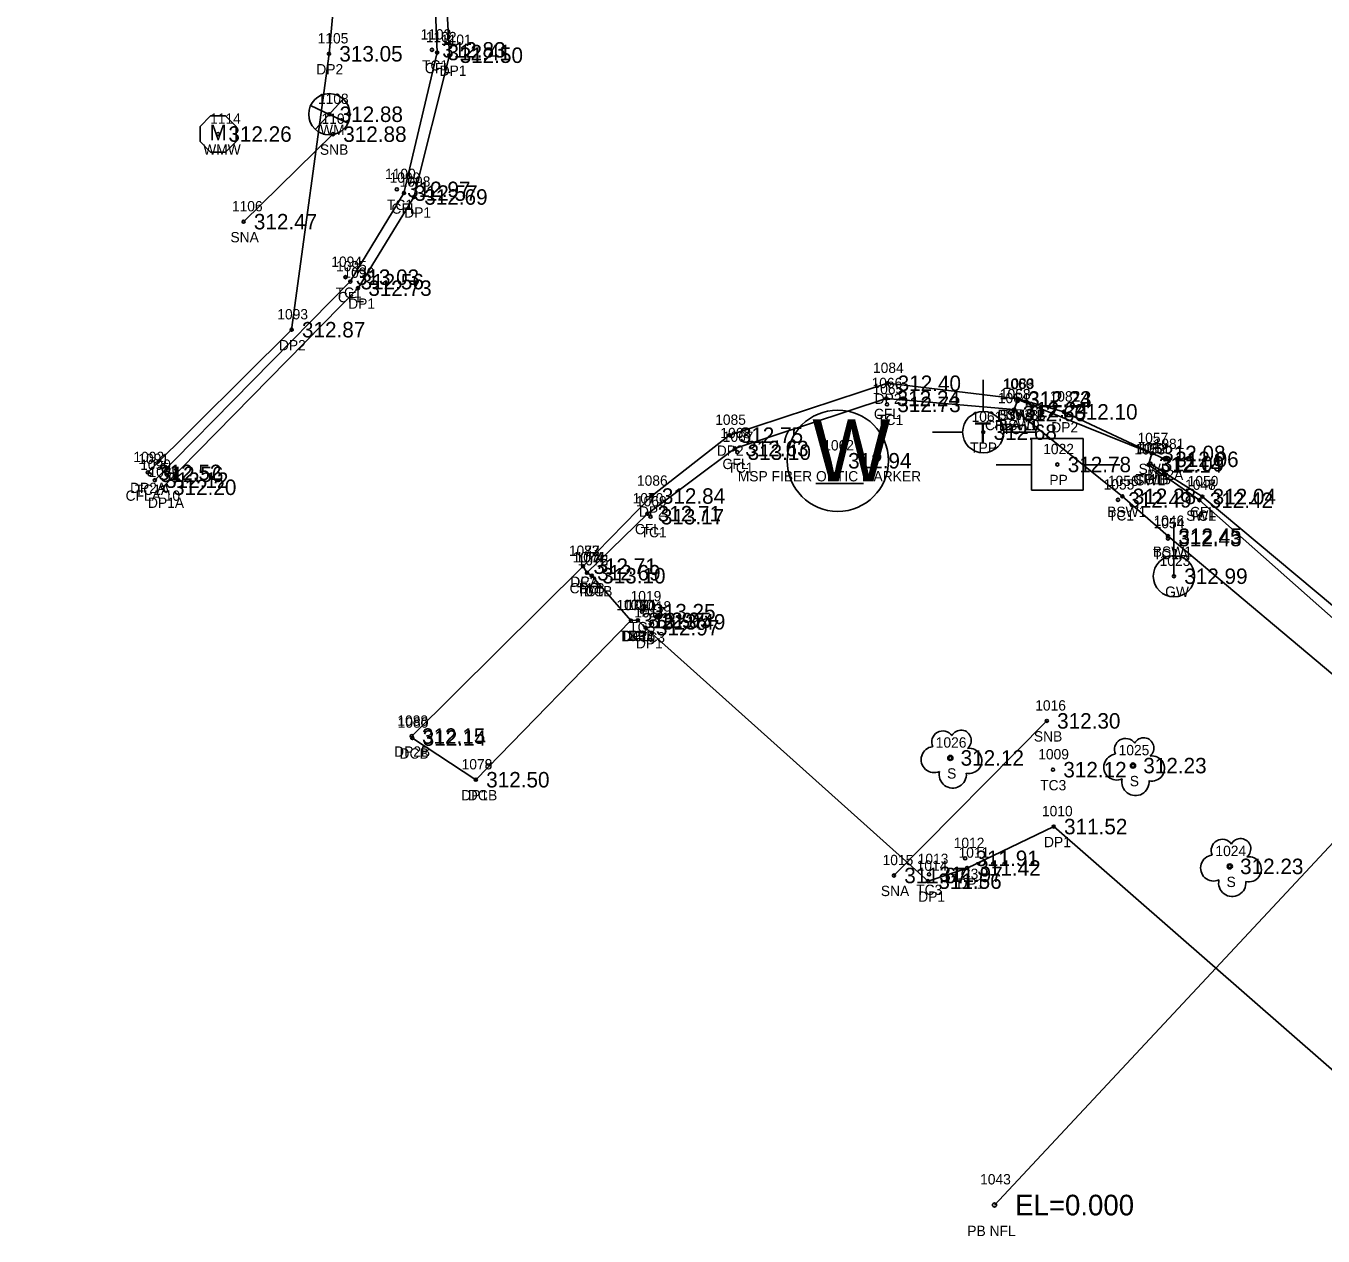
# Model space of a CAD drawing. Extents: x 1970076 to 1971136, y 803126 to 804215.
# Drawn here: x 1970842 to 1970967.7, y 803126.3 to 803243.6 of the extents above; entities that cross this region are included whole.
import ezdxf

# ---------------------------------------------------------------- set-up
doc = ezdxf.new("R2010")
doc.units = 0
for name, color, linetype in [('RD_EX_BldgApp', 7, 'Continuous'), ('RD_EX_BldgApp_txCode', 7, 'Continuous'), ('RD_EX_Conc', 7, 'Continuous'), ('RD_EX_Conc_txCode', 7, 'Continuous'), ('RD_EX_DR_Pipe', 7, 'Continuous'), ('RD_EX_DR_Pipe_txCode', 7, 'Continuous'), ('RD_EX_Driveway', 7, 'Continuous'), ('RD_EX_Driveway_txCode', 7, 'Continuous'), ('RD_EX_Misc_txCode', 7, 'Continuous'), ('RD_EX_SU_H2O', 7, 'Continuous'), ('RD_EX_TX_BldgApp_ELEV', 7, 'Continuous'), ('RD_EX_TX_Conc_ELEV', 7, 'Continuous'), ('RD_EX_TX_Driveway_ELEV', 7, 'Continuous'), ('RD_EX_TX_Misc_ELEV', 7, 'Continuous'), ('RD_EX_TX_UT_ELEV', 7, 'Continuous'), ('RD_EX_TX_VEG_ELEV', 7, 'Continuous'), ('RD_EX_UT', 7, 'Continuous'), ('RD_EX_UT_txCode', 7, 'Continuous'), ('RD_EX_VEG', 7, 'Continuous'), ('RD_EX_VEG_txCode', 7, 'Continuous'), ('RD_HC_Survey_ELEV', 7, 'Continuous'), ('RD_SMD_Locator', 7, 'Continuous'), ('RD_TX_Pipe_ElevEX', 7, 'Continuous')]:
    doc.layers.add(name, color=color, linetype=linetype)

msp = doc.modelspace()

# ---------------------------------------------------------------- linework, layer by layer
at = {"layer": 'RD_EX_BldgApp'}
for p, q in [((1970863.09, 803224.6), (1970871.75, 803233.08)), ((1970926.11, 803161.24), (1970940.92, 803176.22))]:
    msp.add_line(p, q, dxfattribs=at)
at = {"layer": 'RD_EX_Conc'}
for points in [[(1970854.49, 803199.55), (1970873.43, 803218.79), (1970878.63, 803227.37), (1970881.85, 803240.99), (1970881.47, 803250.65), (1970879.58, 803257.38)], [(1970937.76, 803206.39), (1970925.37, 803207.47), (1970910.7, 803202.62), (1970902.22, 803196.3), (1970896.36, 803190.58)], [(1970991.98, 803159.92), (1970984.78, 803166.48), (1970978.42, 803171.68), (1970975.48, 803174.25), (1970971.05, 803178.67), (1970952.67, 803194.12), (1970948.25, 803197.98), (1970937.76, 803206.39), (1970938.1, 803207.37)], [(1970994.79, 803163.51), (1970987.7, 803169.73), (1970983.17, 803172.25), (1970978.99, 803172.48), (1970976.18, 803174.83), (1970975.61, 803177.74), (1970973.48, 803181.89), (1970955.71, 803197.61), (1970950.79, 803201.04), (1970951.1, 803202.14), (1970938.1, 803207.37)], [(1970974.14, 803182.78), (1970955.99, 803197.96), (1970950.97, 803201.14)], [(1970895.99, 803191.21), (1970896.36, 803190.58), (1970896.84, 803190.29), (1970900.63, 803185.94), (1970885.6, 803170.52), (1970879.45, 803174.56)]]:
    msp.add_lwpolyline(points, dxfattribs=at)
at = {"layer": 'RD_EX_DR_Pipe'}
msp.add_line((1970977.83, 803174.26), (1970935.85, 803129.3), dxfattribs=at)
at = {"layer": 'RD_EX_Driveway'}
for points in [[(1970853.81, 803200.3), (1970867.75, 803214.13), (1970871.37, 803240.87), (1970873.32, 803262.28), (1970865.32, 803269.32), (1970865.67, 803269.64), (1970816.24, 803313.45)], [(1970855.26, 803198.86), (1970874.18, 803218.16), (1970879.6, 803226.99), (1970883.03, 803240.73), (1970882.49, 803250.86), (1970880.97, 803256.43), (1970880.48, 803257.86), (1970879.31, 803260.18), (1970873.44, 803270.12)], [(1970952.37, 803201.57), (1970942.58, 803206.17), (1970938.12, 803207.42), (1970925.47, 803208.94), (1970910.17, 803203.91), (1970902.62, 803198.01), (1970895.99, 803191.21), (1970879.38, 803174.75)], [(1970971.84, 803139.57), (1970941.59, 803165.98), (1970933.19, 803161.96), (1970929.41, 803160.69), (1970902.05, 803185.25), (1970901.29, 803185.97), (1970900.63, 803185.94), (1970885.6, 803170.52)]]:
    msp.add_lwpolyline(points, dxfattribs=at)
at = {"layer": 'RD_EX_SU_H2O'}
msp.add_lwpolyline([(1970862.38, 803232.37), (1970862.38, 803233.82), (1970861.35, 803234.85), (1970859.9, 803234.85), (1970858.87, 803233.82), (1970858.87, 803232.37), (1970859.9, 803231.34), (1970861.35, 803231.34)], close=True, dxfattribs=at)
at = {"layer": 'RD_EX_UT'}
for p, q in [((1970870.05, 803233.55), (1970872.72, 803236.45)), ((1970869.57, 803235.85), (1970873.2, 803234.14)), ((1970934.76, 803209.27), (1970934.76, 803206.2)), ((1970929.83, 803204.21), (1970932.76, 803204.21)), ((1970936.76, 803204.21), (1970939.83, 803204.21)), ((1970944.44, 803203.58), (1970939.44, 803203.58)), ((1970939.44, 803203.58), (1970939.44, 803198.58)), ((1970944.44, 803198.58), (1970944.44, 803203.58)), ((1970936.01, 803201.02), (1970939.48, 803201.02)), ((1970944.37, 803201.02), (1970948.01, 803201.02)), ((1970918.54, 803199.22), (1970923.17, 803199.22)), ((1970939.44, 803198.58), (1970944.44, 803198.58)), ((1970953.24, 803190.24), (1970953.24, 803195.24))]:
    msp.add_line(p, q, dxfattribs=at)
for centre, radius in [((1970871.4, 803235.01), 2), ((1970920.67, 803201.43), 4.91), ((1970934.76, 803204.2), 2), ((1970953.24, 803190.24), 2)]:
    msp.add_circle(centre, radius, dxfattribs=at)
at = {"layer": 'RD_EX_VEG'}
for centre in [(1970931.57, 803172.63), (1970949.27, 803171.89), (1970958.65, 803162.12)]:
    msp.add_circle(centre, 0.25, dxfattribs=at)
for centre, radius, start, end in [((1970930.85, 803174.17), 1.08, 34.9763, 204.756), ((1970932.61, 803174.33), 0.995, 308.7626, 152.0467), ((1970930, 803172.47), 1.26, 96.4518, 294.734), ((1970948.55, 803173.44), 1.08, 34.9763, 204.756), ((1970950.31, 803173.59), 0.995, 308.7626, 152.0467), ((1970933.41, 803172.35), 1.22, 256.5667, 98.1046), ((1970947.7, 803171.74), 1.26, 96.4518, 294.734), ((1970951.11, 803171.61), 1.22, 256.5667, 98.1046), ((1970931.81, 803171.03), 1.32, 166.8827, 5.7589), ((1970949.51, 803170.3), 1.32, 166.8827, 5.7589), ((1970959.69, 803163.82), 0.995, 308.7626, 152.0467), ((1970957.93, 803163.67), 1.08, 34.9763, 204.756), ((1970957.08, 803161.96), 1.26, 96.4518, 294.734), ((1970960.49, 803161.84), 1.22, 256.5667, 98.1046), ((1970958.89, 803160.52), 1.32, 166.8827, 5.7589)]:
    msp.add_arc(centre, radius, start, end, dxfattribs=at)
at = {"layer": 'RD_SMD_Locator'}
for centre, radius in [((1970871.37, 803240.87), 0.15), ((1970881.34, 803241.25), 0.15), ((1970881.85, 803240.99), 0.15), ((1970883.03, 803240.73), 0.15), ((1970871.4, 803235.01), 0.15), ((1970860.62, 803233.09), 0.15), ((1970871.75, 803233.08), 0.15), ((1970877.94, 803227.73), 0.15), ((1970878.63, 803227.37), 0.15), ((1970879.6, 803226.99), 0.15), ((1970863.09, 803224.6), 0.15), ((1970872.97, 803219.22), 0.15), ((1970873.43, 803218.79), 0.15), ((1970874.18, 803218.16), 0.15), ((1970867.75, 803214.13), 0.15), ((1970925.47, 803208.94), 0.15), ((1970925.37, 803207.47), 0.15), ((1970938.12, 803207.42), 0.15), ((1970925.44, 803206.89), 0.15), ((1970937.76, 803206.39), 0.15), ((1970937.76, 803206.39), 0.15), ((1970938.1, 803207.37), 0.15), ((1970938.1, 803207.37), 0.15), ((1970942.58, 803206.17), 0.15), ((1970937.59, 803206.01), 0.15), ((1970910.17, 803203.91), 0.15), ((1970934.76, 803204.2), 0.15), ((1970910.7, 803202.62), 0.15), ((1970910.93, 803202.26), 0.15), ((1970950.97, 803201.14), 0.15), ((1970950.97, 803201.14), 0.15), ((1970951.1, 803202.14), 0.15), ((1970952.37, 803201.57), 0.15), ((1970853.81, 803200.3), 0.15), ((1970854, 803200.12), 0.15), ((1970941.95, 803201.07), 0.15), ((1970950.79, 803201.04), 0.15), ((1970854.49, 803199.55), 0.15), ((1970855.26, 803198.86), 0.15), ((1970902.62, 803198.01), 0.15), ((1970947.82, 803197.64), 0.15), ((1970948.25, 803197.98), 0.15), ((1970955.71, 803197.61), 0.15), ((1970955.71, 803197.61), 0.15), ((1970955.99, 803197.96), 0.15), ((1970902.22, 803196.3), 0.15), ((1970902.52, 803196.01), 0.15), ((1970952.66, 803193.89), 0.15), ((1970952.67, 803194.12), 0.15), ((1970895.99, 803191.21), 0.15), ((1970895.99, 803191.21), 0.15), ((1970896.36, 803190.58), 0.15), ((1970896.36, 803190.58), 0.15), ((1970896.84, 803190.29), 0.15), ((1970896.84, 803190.29), 0.15), ((1970953.24, 803190.24), 0.15), ((1970901.69, 803186.81), 0.15), ((1970900.63, 803185.94), 0.15), ((1970900.63, 803185.94), 0.15), ((1970901.29, 803185.97), 0.15), ((1970901.29, 803185.97), 0.15), ((1970902.05, 803185.25), 0.15), ((1970902.64, 803185.82), 0.15), ((1970940.92, 803176.22), 0.15), ((1970879.38, 803174.75), 0.15), ((1970879.45, 803174.56), 0.15), ((1970931.57, 803172.63), 0.15), ((1970941.52, 803171.49), 0.15), ((1970949.27, 803171.89), 0.15), ((1970885.6, 803170.52), 0.15), ((1970885.6, 803170.52), 0.15), ((1970941.59, 803165.98), 0.15), ((1970933.01, 803162.9), 0.15), ((1970926.11, 803161.24), 0.15), ((1970929.51, 803161.35), 0.15), ((1970933.19, 803161.96), 0.15), ((1970958.65, 803162.12), 0.15), ((1970929.41, 803160.69), 0.15), ((1970935.85, 803129.3), 0.2)]:
    msp.add_circle(centre, radius, dxfattribs=at)

# ---------------------------------------------------------------- texts
at = {"layer": 'RD_EX_BldgApp_txCode'}
for s, p in [('1107', (1970870.64, 803234.08)), ('SNB', (1970870.49, 803231.08)), ('1106', (1970861.96, 803225.6)), ('SNA', (1970861.82, 803222.6)), ('1016', (1970939.8, 803177.22)), ('SNB', (1970939.67, 803174.22)), ('1015', (1970925.01, 803162.24)), ('SNA', (1970924.84, 803159.24))]:
    msp.add_text(s, height=1, dxfattribs=at).set_placement(p)
at = {"layer": 'RD_EX_Conc_txCode'}
for s, p in [('1103', (1970880.24, 803242.25)), ('1102', (1970880.75, 803241.99)), ('TC1', (1970880.38, 803239.25)), ('CFL', (1970880.65, 803238.99)), ('1100', (1970876.8, 803228.73)), ('1099', (1970877.24, 803228.37)), ('TC1', (1970876.98, 803225.73)), ('CFL', (1970877.42, 803225.37)), ('1094', (1970871.59, 803220.22)), ('1095', (1970872.05, 803219.79)), ('TC1', (1970872.01, 803217.22)), ('CFL', (1970872.23, 803216.79)), ('1066', (1970923.94, 803208.47)), ('1065', (1970924.03, 803207.89)), ('1060', (1970936.65, 803208.37)), ('1059', (1970936.71, 803208.37)), ('1064', (1970936.18, 803207.01)), ('1063', (1970936.36, 803207.39)), ('1058', (1970936.38, 803207.39)), ('CFL', (1970924.17, 803205.47)), ('BSW1B', (1970936.14, 803205.37)), ('SWLB', (1970936.33, 803205.37)), ('TC1', (1970924.48, 803204.89)), ('CFLA 10', (1970934.93, 803204.39)), ('BSW1', (1970936.28, 803204.39)), ('TC1', (1970936.62, 803204.01)), ('1068', (1970909.29, 803203.62)), ('1067', (1970909.52, 803203.26)), ('1057', (1970949.71, 803203.14)), ('1053', (1970949.4, 803202.04)), ('1052', (1970949.59, 803202.14)), ('1051', (1970949.87, 803202.14)), ('1091', (1970852.89, 803201.12)), ('1090', (1970853.07, 803200.55)), ('CFL', (1970909.49, 803200.62)), ('TC1', (1970909.97, 803200.26)), ('1056', (1970946.84, 803198.98)), ('CFLB', (1970949.29, 803199.14)), ('SWL', (1970949.5, 803199.04)), ('TC1B', (1970949.54, 803199.14)), ('SWL', (1970949.81, 803200.14)), ('TC1A', (1970852.55, 803198.12)), ('1055', (1970946.43, 803198.64)), ('1047', (1970954.32, 803198.61)), ('1048', (1970954.32, 803198.61)), ('1050', (1970954.57, 803198.96)), ('CFLA 10', (1970851.66, 803197.55)), ('1070', (1970900.79, 803197.3)), ('1069', (1970901.11, 803197.01)), ('BSW1', (1970946.77, 803195.98)), ('TC1', (1970946.85, 803195.64)), ('SWL', (1970954.42, 803195.61)), ('TC1', (1970954.75, 803195.61)), ('CFL', (1970954.79, 803195.96)), ('CFL', (1970901.01, 803194.3)), ('TC1', (1970901.56, 803194.01)), ('1046', (1970951.26, 803195.12)), ('1054', (1970951.27, 803194.89)), ('1073', (1970894.61, 803192.21)), ('1074', (1970894.97, 803191.58)), ('1071', (1970895.26, 803191.58)), ('TC1A', (1970951.21, 803191.89)), ('BSW1', (1970951.19, 803192.12)), ('1072', (1970895.46, 803191.29)), ('1075', (1970895.46, 803191.29)), ('DCA', (1970894.73, 803189.21)), ('CFLB', (1970894.68, 803188.58)), ('TC1B', (1970895.41, 803188.29)), ('DC', (1970895.58, 803188.58)), ('DC', (1970896.06, 803188.29)), ('1019', (1970900.59, 803187.81)), ('1076', (1970899.22, 803186.94)), ('1020', (1970899.86, 803186.97)), ('1018', (1970901.54, 803186.82)), ('TC3B', (1970899.57, 803183.97)), ('DC', (1970899.85, 803183.94)), ('TC3', (1970900.45, 803184.81)), ('TC3', (1970901.4, 803183.82)), ('1080', (1970878.03, 803175.56)), ('DCB', (1970878.2, 803172.56)), ('1079', (1970884.22, 803171.52)), ('1009', (1970940.09, 803172.49)), ('TC3', (1970940.28, 803169.49)), ('DC', (1970884.82, 803168.52)), ('1012', (1970931.9, 803163.9)), ('1013', (1970928.41, 803162.35)), ('TC3', (1970931.76, 803160.9)), ('TC3', (1970928.27, 803159.35))]:
    msp.add_text(s, height=1, dxfattribs=at).set_placement(p)
at = {"layer": 'RD_EX_DR_Pipe_txCode'}
for s, p in [('1043', (1970934.46, 803131.3)), ('PB NFL', (1970933.22, 803126.3))]:
    msp.add_text(s, height=1, dxfattribs=at).set_placement(p)
at = {"layer": 'RD_EX_Driveway_txCode'}
for s, p in [('1105', (1970870.27, 803241.87)), ('1101', (1970882.22, 803241.73)), ('DP2', (1970870.14, 803238.87)), ('DP1', (1970882.09, 803238.73)), ('1098', (1970878.22, 803227.99)), ('DP1', (1970878.66, 803224.99)), ('1096', (1970872.77, 803219.16)), ('DP1', (1970873.23, 803216.16)), ('1093', (1970866.36, 803215.13)), ('DP2', (1970866.52, 803212.13)), ('1084', (1970924.08, 803209.94)), ('1083', (1970936.73, 803208.42)), ('DP2', (1970924.24, 803206.94)), ('1082', (1970941.19, 803207.17)), ('DP2', (1970936.89, 803205.42)), ('1085', (1970908.79, 803204.91)), ('DP2', (1970941.35, 803204.17)), ('DP2', (1970908.94, 803201.91)), ('1081', (1970951.27, 803202.57)), ('1092', (1970852.42, 803201.3)), ('1089', (1970853.88, 803199.86)), ('1086', (1970901.21, 803199.01)), ('DP2A', (1970950.65, 803199.57)), ('DP2A', (1970852.09, 803198.3)), ('DP1A', (1970853.83, 803196.86)), ('DP2', (1970901.4, 803196.01)), ('1087', (1970894.61, 803192.21)), ('DP2', (1970894.76, 803189.21)), ('1077', (1970899.24, 803186.94)), ('1021', (1970900.18, 803186.97)), ('1017', (1970900.95, 803186.25)), ('DP1', (1970899.68, 803183.94)), ('DP1', (1970900.34, 803183.97)), ('DP1', (1970901.11, 803183.25)), ('1088', (1970877.99, 803175.75)), ('DP2B', (1970877.68, 803172.75)), ('1078', (1970884.22, 803171.52)), ('DP1B', (1970884.18, 803168.52)), ('1010', (1970940.45, 803166.98)), ('DP1', (1970940.65, 803163.98)), ('1011', (1970932.37, 803162.96)), ('1014', (1970928.31, 803161.69)), ('DP1', (1970932.25, 803159.96)), ('DP1', (1970928.46, 803158.69))]:
    msp.add_text(s, height=1, dxfattribs=at).set_placement(p)
at = {"layer": 'RD_EX_Misc_txCode'}
for s, p in [('1114', (1970859.85, 803234.09)), ('WMW', (1970859.18, 803231.09)), ('1062', (1970919.26, 803202.43)), ('MSP FIBER OPTIC MARKER', (1970910.98, 803199.43))]:
    msp.add_text(s, height=1, dxfattribs=at).set_placement(p)
at = {"layer": 'RD_EX_SU_H2O'}
msp.add_text('M', height=1.5, dxfattribs=at).set_placement((1970859.79, 803232.49))
at = {"layer": 'RD_EX_TX_BldgApp_ELEV'}
for s, p in [('312.88', (1970872.75, 803232.33)), ('312.47', (1970864.09, 803223.85)), ('312.30', (1970941.92, 803175.47)), ('311.67', (1970927.11, 803160.49))]:
    msp.add_text(s, height=1.5, dxfattribs=at).set_placement(p)
at = {"layer": 'RD_EX_TX_Conc_ELEV'}
for s, p in [('312.83', (1970882.34, 803240.5)), ('312.41', (1970882.85, 803240.24)), ('312.97', (1970878.94, 803226.98)), ('312.57', (1970879.63, 803226.62)), ('313.03', (1970873.97, 803218.47)), ('312.56', (1970874.43, 803218.04)), ('312.24', (1970926.37, 803206.72)), ('312.73', (1970926.44, 803206.14)), ('312.24', (1970939.1, 803206.62)), ('312.24', (1970939.1, 803206.62)), ('312.60', (1970938.59, 803205.26)), ('312.24', (1970938.76, 803205.64)), ('312.24', (1970938.76, 803205.64)), ('312.63', (1970911.7, 803201.87)), ('313.10', (1970911.93, 803201.51)), ('312.08', (1970952.1, 803201.39)), ('312.14', (1970951.79, 803200.29)), ('312.09', (1970951.97, 803200.39)), ('312.09', (1970951.97, 803200.39)), ('312.56', (1970855, 803199.37)), ('312.12', (1970855.49, 803198.8)), ('312.28', (1970949.25, 803197.23)), ('312.49', (1970948.82, 803196.89)), ('312.42', (1970956.71, 803196.86)), ('312.42', (1970956.71, 803196.86)), ('312.04', (1970956.99, 803197.21)), ('312.71', (1970903.22, 803195.55)), ('313.17', (1970903.52, 803195.26)), ('312.43', (1970953.66, 803193.14)), ('312.45', (1970953.67, 803193.37)), ('312.71', (1970896.99, 803190.46)), ('312.69', (1970897.36, 803189.83)), ('312.69', (1970897.36, 803189.83)), ('313.10', (1970897.84, 803189.54)), ('313.10', (1970897.84, 803189.54)), ('313.25', (1970902.69, 803186.06)), ('312.97', (1970901.63, 803185.19)), ('312.95', (1970902.29, 803185.22)), ('313.49', (1970903.64, 803185.07)), ('312.14', (1970880.45, 803173.81)), ('312.50', (1970886.6, 803169.77)), ('312.12', (1970942.52, 803170.74)), ('311.91', (1970934.01, 803162.15)), ('311.97', (1970930.51, 803160.6))]:
    msp.add_text(s, height=1.5, dxfattribs=at).set_placement(p)
at = {"layer": 'RD_EX_TX_Driveway_ELEV'}
for s, p in [('313.05', (1970872.37, 803240.12)), ('312.50', (1970884.03, 803239.98)), ('312.69', (1970880.6, 803226.24)), ('312.73', (1970875.18, 803217.41)), ('312.87', (1970868.75, 803213.38)), ('312.40', (1970926.47, 803208.19)), ('312.23', (1970939.12, 803206.67)), ('312.10', (1970943.58, 803205.42)), ('312.75', (1970911.17, 803203.16)), ('312.06', (1970953.37, 803200.82)), ('312.52', (1970854.81, 803199.55)), ('312.20', (1970856.26, 803198.11)), ('312.84', (1970903.62, 803197.26)), ('312.71', (1970896.99, 803190.46)), ('312.97', (1970901.63, 803185.19)), ('312.95', (1970902.29, 803185.22)), ('312.97', (1970903.05, 803184.5)), ('312.15', (1970880.38, 803174)), ('312.50', (1970886.6, 803169.77)), ('311.52', (1970942.59, 803165.23)), ('311.42', (1970934.19, 803161.21)), ('311.56', (1970930.41, 803159.94))]:
    msp.add_text(s, height=1.5, dxfattribs=at).set_placement(p)
at = {"layer": 'RD_EX_TX_Misc_ELEV'}
for s, p in [('312.26', (1970861.62, 803232.34)), ('312.94', (1970921.67, 803200.68))]:
    msp.add_text(s, height=1.5, dxfattribs=at).set_placement(p)
at = {"layer": 'RD_EX_TX_UT_ELEV'}
for s, p in [('312.88', (1970872.4, 803234.26)), ('312.68', (1970935.76, 803203.45)), ('312.99', (1970954.24, 803189.49))]:
    msp.add_text(s, height=1.5, dxfattribs=at).set_placement(p)
at = {"layer": 'RD_EX_TX_VEG_ELEV'}
for s, p in [('312.12', (1970932.57, 803171.88)), ('312.23', (1970950.27, 803171.14)), ('312.23', (1970959.65, 803161.37))]:
    msp.add_text(s, height=1.5, dxfattribs=at).set_placement(p)
at = {"layer": 'RD_EX_UT'}
for s, height, p in [('W', 6, (1970918.2, 803199.43)), ('T', 2, (1970933.91, 803203.15))]:
    msp.add_text(s, height=height, dxfattribs=at).set_placement(p)
at = {"layer": 'RD_EX_UT_txCode'}
for s, p in [('1108', (1970870.3, 803236.01)), ('WM', (1970870.5, 803233.01)), ('1061', (1970933.63, 803205.2)), ('TPP', (1970933.49, 803202.2)), ('1022', (1970940.57, 803202.07)), ('PP', (1970941.17, 803199.07)), ('1023', (1970951.85, 803191.24)), ('GW', (1970952.39, 803188.24))]:
    msp.add_text(s, height=1, dxfattribs=at).set_placement(p)
at = {"layer": 'RD_EX_VEG_txCode'}
for s, p in [('1026', (1970930.16, 803173.63)), ('1025', (1970947.88, 803172.89)), ('S', (1970931.26, 803170.63)), ('S', (1970948.96, 803169.89)), ('1024', (1970957.26, 803163.12)), ('S', (1970958.34, 803160.12))]:
    msp.add_text(s, height=1, dxfattribs=at).set_placement(p)
at = {"layer": 'RD_HC_Survey_ELEV'}
msp.add_text('312.78', height=1.5, dxfattribs=at).set_placement((1970942.95, 803200.32))
at = {"layer": 'RD_TX_Pipe_ElevEX'}
msp.add_text('EL=0.000', height=2, dxfattribs=at).set_placement((1970937.85, 803128.3))

doc.saveas('drawing.dxf')
